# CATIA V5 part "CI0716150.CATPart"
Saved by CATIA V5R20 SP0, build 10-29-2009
Part number: CI071615150_ASM
Bounding box of the stored display mesh (mm): x -15 to 15, y -15.201 to 17.744, z -174 to 11.845
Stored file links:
  C:\Users\Raffaele\Desktop\3D X SITO CF\BOLEX\19-INCLINED ASSEMBLY REF_CI\CI0716150.CATPart
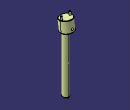
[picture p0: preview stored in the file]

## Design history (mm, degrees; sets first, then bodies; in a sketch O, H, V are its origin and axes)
Set1
  DatumSurface1 to DatumSurface16 "MANIFOLD_SOLID_BREP #385"
  DatumSurface17 to DatumSurface39 "MANIFOLD_SOLID_BREP #1110"
Body1 (main body)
